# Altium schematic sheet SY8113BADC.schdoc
size 127 x 101 mm
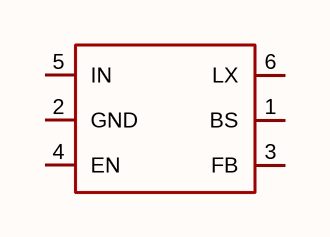
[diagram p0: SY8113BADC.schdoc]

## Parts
U?  sy8113badc  [TSOT-23-6_L2.9-W1.6-P0.95-LS2.8-BR]  (value not drawn)

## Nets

Not connected (* = marked no-connect by the designer): U? 1(BS) 2(GND) 3(FB) 4(EN) 5(IN) 6(LX)

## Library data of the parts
U? = sy8113badc: 功能类型:降压型;工作电压:4.5V~18V;输出电压:-;输出电流:3A;输出类型:可调;; Manufacturer: Silergy(矽力杰); AddInBom: yes; ModelId: 2c4039b5b88644c1bda4b4ba9e971667; ModelName: TSOT-23-6_L2.9-W1.6-H1.1-LS2.8-P0.95; ModelTransform: 110.45568,114.173,0,180,0,0,-0.005,-0.0005,0; Function: 降压型; Output Current: 3A; Frequency - Switching: 500kHz; Synchronous Rectifier: 是; Number of Outputs: 1; Topology: 降压式; Quiescent Current: 100uA; Switch tube (built-in/external): 内置; Output Type: 可调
